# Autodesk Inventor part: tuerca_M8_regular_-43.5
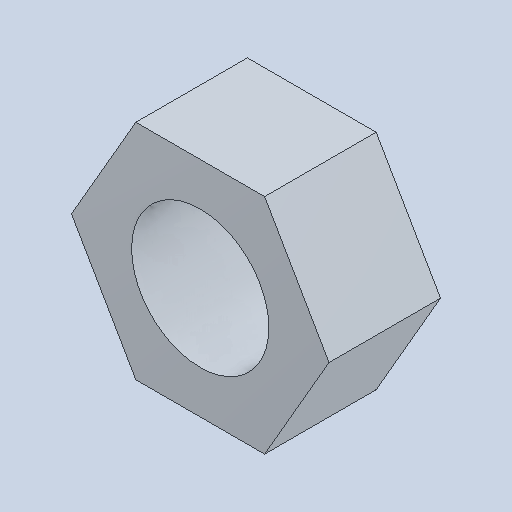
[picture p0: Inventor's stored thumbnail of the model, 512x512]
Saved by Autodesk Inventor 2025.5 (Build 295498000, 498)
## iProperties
Created: 2026-10
Part Number: tuerca_M8_regular_-43.5
Material: Genérico
Document SubType Name: Modeling
Designer: Luis M
Density: 1 g/cm^3
Appearance: Valor por defecto
Author: Luis M
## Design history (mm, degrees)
feature "Base1"
node "Sólido1"
